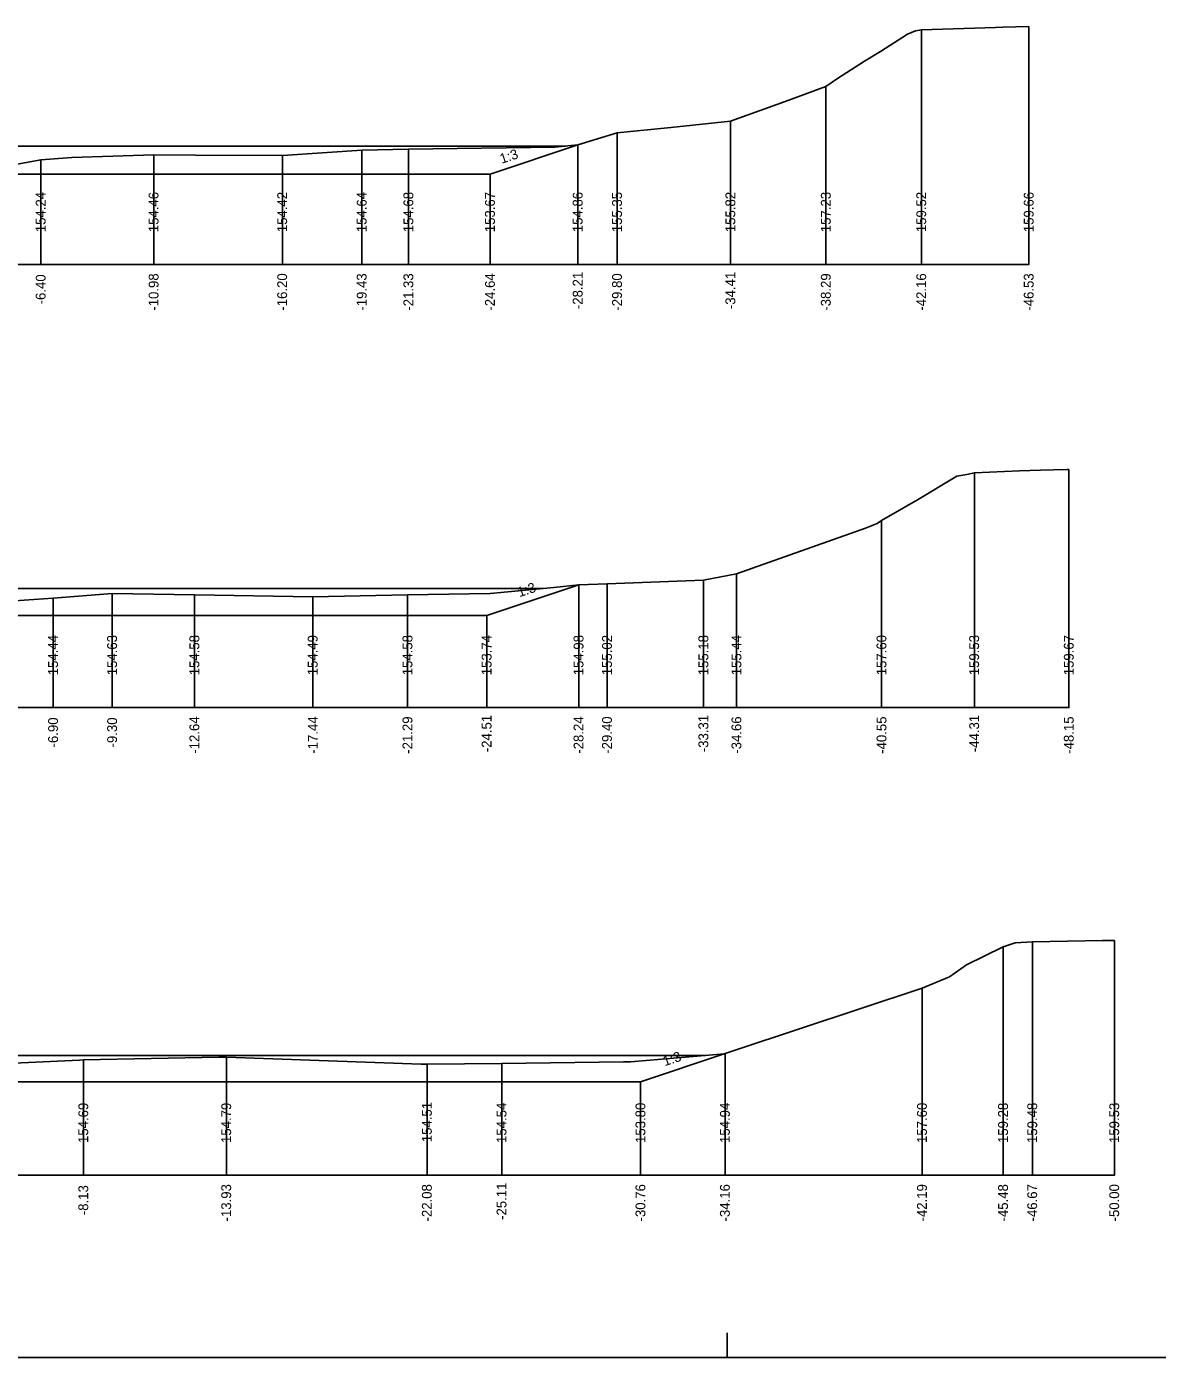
# Model space of a CAD drawing. Extents: x -582678 to -581845, y -1210354 to -1210235.
# Drawn here: x -582622 to -582576, y -1210354.1 to -1210300 of the extents above; entities that cross this region are included whole.
import ezdxf

# ---------------------------------------------------------------- set-up
doc = ezdxf.new("R2010")
doc.units = 0
for name, color, linetype in [('8', 7, 'Continuous'), ('_N_popis', 7, 'Continuous'), ('_N_tučná', 7, 'Continuous'), ('_rámeček', 7, 'Continuous'), ('_S_hladina', 7, 'Continuous'), ('_S_popis', 7, 'Continuous'), ('_S_tenká', 7, 'Continuous'), ('_S_velmi_tenká', 7, 'Continuous')]:
    doc.layers.add(name, color=color, linetype=linetype)

msp = doc.modelspace()

# ---------------------------------------------------------------- linework, layer by layer
at = {"layer": '_N_popis'}
for points in [[(-582599.565, -1210304.834), (-582599.565, -1210309.691), (-582599.565, -1210309.691), (-582599.565, -1210309.691)], [(-582603.128, -1210306.021), (-582603.128, -1210309.691), (-582603.128, -1210309.691), (-582603.128, -1210309.691)], [(-582599.531, -1210322.706), (-582599.531, -1210327.691), (-582599.531, -1210327.691), (-582599.531, -1210327.691)], [(-582603.264, -1210323.951), (-582603.264, -1210327.691), (-582603.264, -1210327.691), (-582603.264, -1210327.691)], [(-582593.586, -1210341.748), (-582593.586, -1210346.691), (-582593.586, -1210346.691), (-582593.586, -1210346.691)], [(-582597.016, -1210342.891), (-582597.016, -1210346.691), (-582597.016, -1210346.691), (-582597.016, -1210346.691)]]:
    msp.add_lwpolyline(points, dxfattribs=at)
at = {"layer": '_N_tučná'}
for p, q in [((-582599.565, -1210304.834), (-582603.128, -1210306.021)), ((-582599.531, -1210322.706), (-582603.264, -1210323.951)), ((-582593.586, -1210341.748), (-582597.016, -1210342.891))]:
    msp.add_line(p, q, dxfattribs=at)
for points in [[(-582603.128, -1210306.021), (-582647.594, -1210306.021)], [(-582603.264, -1210323.951), (-582649.48, -1210323.951)], [(-582597.016, -1210342.891), (-582652.343, -1210342.891)]]:
    msp.add_lwpolyline(points, dxfattribs=at)
at = {"layer": '_rámeček'}
for p, q in [((-582593.502, -1210353.091), (-582593.502, -1210354.091)), ((-582677.502, -1210354.091), (-582467.502, -1210354.091))]:
    msp.add_line(p, q, dxfattribs=at)
at = {"layer": '_S_hladina'}
for points in [[(-582649.957, -1210304.881), (-582600.057, -1210304.881)], [(-582652.78, -1210322.851), (-582600.971, -1210322.851)], [(-582655.532, -1210341.821), (-582594.384, -1210341.821)]]:
    msp.add_lwpolyline(points, dxfattribs=at)
at = {"layer": '_S_tenká'}
for p, q in [((-582581.245, -1210309.691), (-582665.531, -1210309.691)), ((-582579.618, -1210327.691), (-582667.048, -1210327.691)), ((-582577.772, -1210346.691), (-582670.549, -1210346.691))]:
    msp.add_line(p, q, dxfattribs=at)
for points in [[(-582581.245, -1210300.03), (-582582.299, -1210300.052), (-582582.607, -1210300.061), (-582585.611, -1210300.167), (-582585.857, -1210300.199), (-582586.18, -1210300.34), (-582587.275, -1210301.036), (-582587.926, -1210301.44), (-582589.025, -1210302.135), (-582589.487, -1210302.46), (-582591.15, -1210303.075), (-582593.362, -1210303.871), (-582595.783, -1210304.13), (-582597.967, -1210304.341), (-582599.565, -1210304.834), (-582600.499, -1210304.924), (-582606.441, -1210305.009), (-582608.338, -1210305.055), (-582611.567, -1210305.271), (-582615.098, -1210305.256), (-582616.79, -1210305.232), (-582620.12, -1210305.348), (-582621.376, -1210305.448), (-582623.076, -1210305.756)], [(-582579.618, -1210318.025), (-582579.687, -1210318.016), (-582580.25, -1210318.036), (-582580.778, -1210318.043), (-582581.627, -1210318.07), (-582583.461, -1210318.157), (-582583.761, -1210318.218), (-582584.177, -1210318.29), (-582585.776, -1210319.248), (-582587.225, -1210320.087), (-582587.408, -1210320.222), (-582587.879, -1210320.407), (-582593.116, -1210322.256), (-582594.459, -1210322.511), (-582598.374, -1210322.669), (-582599.531, -1210322.706), (-582600.541, -1210322.81), (-582603.123, -1210323.056), (-582606.477, -1210323.109), (-582610.327, -1210323.201), (-582615.132, -1210323.107), (-582618.474, -1210323.057), (-582620.872, -1210323.248), (-582624.812, -1210323.519)], [(-582577.772, -1210337.161), (-582578.262, -1210337.152), (-582581.104, -1210337.214), (-582581.802, -1210337.257), (-582582.289, -1210337.41), (-582583.776, -1210338.147), (-582584.475, -1210338.632), (-582585.582, -1210339.091), (-582593.091, -1210341.585), (-582593.586, -1210341.748), (-582593.614, -1210341.754), (-582597.42, -1210342.086), (-582597.707, -1210342.089), (-582602.658, -1210342.147), (-582605.691, -1210342.182), (-582605.815, -1210342.178), (-582605.925, -1210342.173), (-582613.84, -1210341.897), (-582614.146, -1210341.9), (-582619.645, -1210341.997), (-582619.807, -1210342.023), (-582624.559, -1210342.231)]]:
    msp.add_lwpolyline(points, dxfattribs=at)
at = {"layer": '_S_velmi_tenká'}
for points in [[(-582581.245, -1210300.03), (-582581.245, -1210309.691), (-582581.245, -1210309.691), (-582581.245, -1210309.691)], [(-582585.611, -1210300.167), (-582585.611, -1210309.691), (-582585.611, -1210309.691), (-582585.611, -1210309.691)], [(-582589.487, -1210302.46), (-582589.487, -1210309.691), (-582589.487, -1210309.691), (-582589.487, -1210309.691)], [(-582593.362, -1210303.871), (-582593.362, -1210309.691), (-582593.362, -1210309.691), (-582593.362, -1210309.691)], [(-582597.967, -1210304.341), (-582597.967, -1210309.691), (-582597.967, -1210309.691), (-582597.967, -1210309.691)], [(-582606.441, -1210305.009), (-582606.441, -1210309.691), (-582606.441, -1210309.691), (-582606.441, -1210309.691)], [(-582621.376, -1210305.448), (-582621.376, -1210309.691), (-582621.376, -1210309.691), (-582621.376, -1210309.691)], [(-582616.79, -1210305.232), (-582616.79, -1210309.691), (-582616.79, -1210309.691), (-582616.79, -1210309.691)], [(-582611.567, -1210305.271), (-582611.567, -1210309.691), (-582611.567, -1210309.691), (-582611.567, -1210309.691)], [(-582608.338, -1210305.055), (-582608.338, -1210309.691), (-582608.338, -1210309.691), (-582608.338, -1210309.691)], [(-582583.461, -1210318.157), (-582583.461, -1210327.691), (-582583.461, -1210327.691), (-582583.461, -1210327.691)], [(-582579.618, -1210318.025), (-582579.618, -1210327.691), (-582579.618, -1210327.691), (-582579.618, -1210327.691)], [(-582587.225, -1210320.087), (-582587.225, -1210327.691), (-582587.225, -1210327.691), (-582587.225, -1210327.691)], [(-582593.116, -1210322.256), (-582593.116, -1210327.691), (-582593.116, -1210327.691), (-582593.116, -1210327.691)], [(-582598.374, -1210322.669), (-582598.374, -1210327.691), (-582598.374, -1210327.691), (-582598.374, -1210327.691)], [(-582594.459, -1210322.511), (-582594.459, -1210327.691), (-582594.459, -1210327.691), (-582594.459, -1210327.691)], [(-582620.872, -1210323.248), (-582620.872, -1210327.691), (-582620.872, -1210327.691), (-582620.872, -1210327.691)], [(-582618.474, -1210323.057), (-582618.474, -1210327.691), (-582618.474, -1210327.691), (-582618.474, -1210327.691)], [(-582615.132, -1210323.107), (-582615.132, -1210327.691), (-582615.132, -1210327.691), (-582615.132, -1210327.691)], [(-582610.327, -1210323.201), (-582610.327, -1210327.691), (-582610.327, -1210327.691), (-582610.327, -1210327.691)], [(-582606.477, -1210323.109), (-582606.477, -1210327.691), (-582606.477, -1210327.691), (-582606.477, -1210327.691)], [(-582582.289, -1210337.41), (-582582.289, -1210346.691), (-582582.289, -1210346.691), (-582582.289, -1210346.691)], [(-582581.104, -1210337.214), (-582581.104, -1210346.691), (-582581.104, -1210346.691), (-582581.104, -1210346.691)], [(-582577.772, -1210337.161), (-582577.772, -1210346.691), (-582577.772, -1210346.691), (-582577.772, -1210346.691)], [(-582585.582, -1210339.091), (-582585.582, -1210346.691), (-582585.582, -1210346.691), (-582585.582, -1210346.691)], [(-582619.645, -1210341.997), (-582619.645, -1210346.691), (-582619.645, -1210346.691), (-582619.645, -1210346.691)], [(-582613.84, -1210341.897), (-582613.84, -1210346.691), (-582613.84, -1210346.691), (-582613.84, -1210346.691)], [(-582605.691, -1210342.182), (-582605.691, -1210346.691), (-582605.691, -1210346.691), (-582605.691, -1210346.691)], [(-582602.658, -1210342.147), (-582602.658, -1210346.691), (-582602.658, -1210346.691), (-582602.658, -1210346.691)]]:
    msp.add_lwpolyline(points, dxfattribs=at)

# ---------------------------------------------------------------- texts
at = {"layer": '8'}
msp.add_text('-', height=6.000000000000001e-11, dxfattribs=at).set_placement((-582577.772, -1210346.691))
at = {"layer": '_N_popis'}
for s, rotation, p in [('1:3', 18.4349, (-582602.655, -1210305.603)), ('153.67', 90, (-582602.935, -1210308.381)), ('154.86', 90, (-582599.372, -1210308.381)), ('-24.64', 90, (-582602.935, -1210311.568)), ('-28.21', 90, (-582599.372, -1210311.506)), ('1:3', 18.4349, (-582601.938, -1210323.212)), ('153.74', 90, (-582603.071, -1210326.381)), ('154.98', 90, (-582599.337, -1210326.382)), ('-24.51', 90, (-582603.071, -1210329.506)), ('-28.24', 90, (-582599.337, -1210329.568)), ('1:3', 18.4349, (-582596.033, -1210342.265)), ('153.80', 90, (-582596.822, -1210345.381)), ('154.94', 90, (-582593.393, -1210345.381)), ('-30.76', 90, (-582596.822, -1210348.569)), ('-34.16', 90, (-582593.393, -1210348.569))]:
    msp.add_text(s, height=0.4, rotation=rotation, dxfattribs=at).set_placement(p)
at = {"layer": '_S_popis'}
for s, p in [('154.24', (-582621.183, -1210308.381)), ('154.46', (-582616.597, -1210308.381)), ('154.42', (-582611.374, -1210308.38)), ('154.64', (-582608.145, -1210308.381)), ('154.68', (-582606.247, -1210308.382)), ('155.35', (-582597.774, -1210308.382)), ('155.82', (-582593.169, -1210308.38)), ('157.23', (-582589.294, -1210308.381)), ('159.52', (-582585.418, -1210308.38)), ('159.66', (-582581.052, -1210308.381)), ('-6.40', (-582621.183, -1210311.313)), ('-10.98', (-582616.597, -1210311.57)), ('-16.20', (-582611.374, -1210311.568)), ('-19.43', (-582608.145, -1210311.569)), ('-21.33', (-582606.247, -1210311.569)), ('-29.80', (-582597.774, -1210311.568)), ('-34.41', (-582593.169, -1210311.506)), ('-38.29', (-582589.294, -1210311.57)), ('-42.16', (-582585.418, -1210311.569)), ('-46.53', (-582581.052, -1210311.569)), ('154.44', (-582620.679, -1210326.381)), ('154.63', (-582618.281, -1210326.381)), ('154.58', (-582614.939, -1210326.382)), ('154.49', (-582610.134, -1210326.382)), ('154.58', (-582606.284, -1210326.382)), ('155.02', (-582598.181, -1210326.38)), ('155.18', (-582594.266, -1210326.382)), ('155.44', (-582592.923, -1210326.381)), ('157.60', (-582587.032, -1210326.381)), ('159.53', (-582583.268, -1210326.381)), ('159.67', (-582579.425, -1210326.381)), ('-6.90', (-582620.679, -1210329.313)), ('-9.30', (-582618.281, -1210329.313)), ('-12.64', (-582614.939, -1210329.568)), ('-17.44', (-582610.127, -1210329.568)), ('-21.29', (-582606.284, -1210329.57)), ('-29.40', (-582598.181, -1210329.568)), ('-33.31', (-582594.266, -1210329.506)), ('-34.66', (-582592.923, -1210329.569)), ('-40.55', (-582587.032, -1210329.571)), ('-44.31', (-582583.268, -1210329.506)), ('-48.15', (-582579.425, -1210329.571)), ('154.69', (-582619.452, -1210345.382)), ('154.79', (-582613.647, -1210345.382)), ('154.51', (-582605.498, -1210345.349)), ('154.54', (-582602.465, -1210345.381)), ('157.60', (-582585.389, -1210345.381)), ('159.28', (-582582.095, -1210345.382)), ('159.48', (-582580.91, -1210345.382)), ('159.53', (-582577.579, -1210345.381)), ('-8.13', (-582619.452, -1210348.314)), ('-13.93', (-582613.647, -1210348.569)), ('-22.08', (-582605.498, -1210348.57)), ('-25.11', (-582602.465, -1210348.506)), ('-42.19', (-582585.389, -1210348.57)), ('-45.48', (-582582.095, -1210348.57)), ('-46.67', (-582580.91, -1210348.569)), ('-50.00', (-582577.579, -1210348.568))]:
    msp.add_text(s, height=0.4, rotation=90, dxfattribs=at).set_placement(p)

doc.saveas('drawing.dxf')
